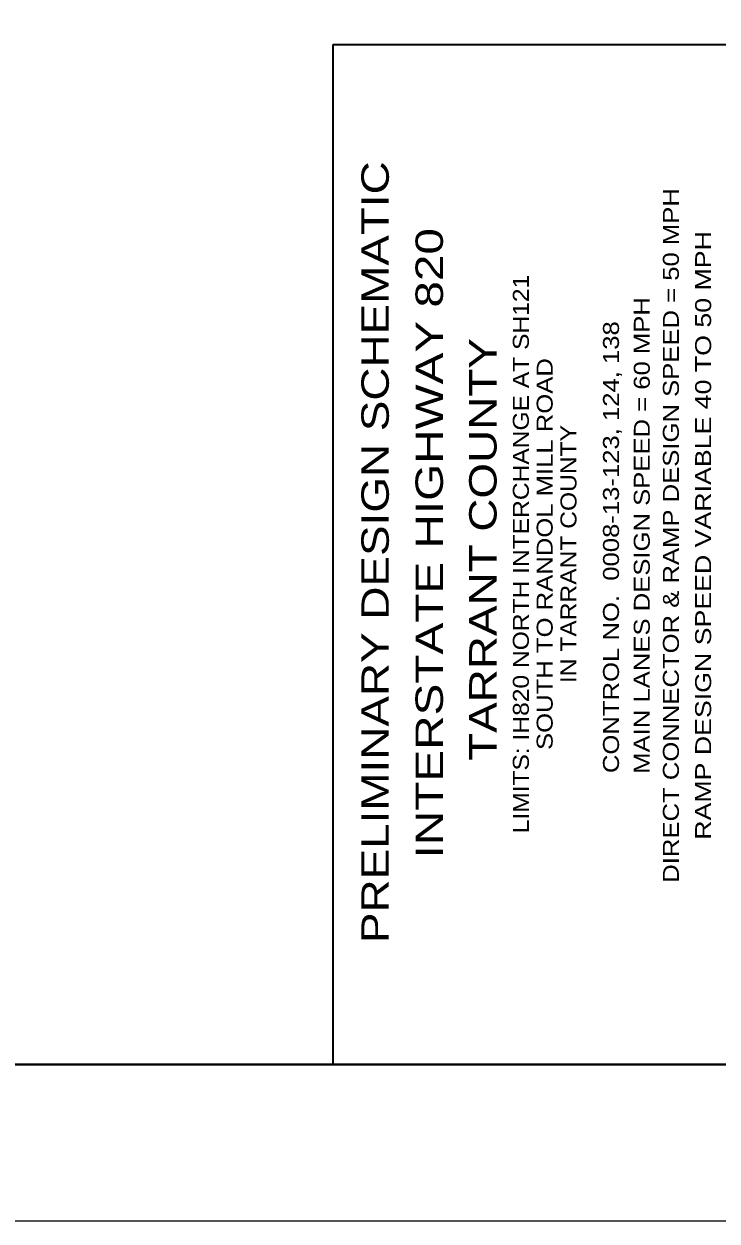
# Model space of a CAD drawing. Extents: x 2363323 to 2367082, y 6956018 to 6980837.
# Drawn here: x 2366029 to 2366472, y 6957201 to 6957965 of the extents above; entities that cross this region are included whole.
import ezdxf
from ezdxf.enums import TextEntityAlignment as Align

# ---------------------------------------------------------------- set-up
doc = ezdxf.new("R2010")
doc.units = 0
doc.header["$LTSCALE"] = 4.1
for name, color, linetype, lineweight in [('61', 7, 'Continuous', 40), ('62', 7, 'Continuous', 13), ('63', 7, 'Continuous', 13)]:
    doc.layers.add(name, color=color, linetype=linetype, lineweight=lineweight)

msp = doc.modelspace()

# ---------------------------------------------------------------- linework, layer by layer
at = {"layer": '61'}
msp.add_line((2366823.34, 6957300.912), (2363423.186, 6957300.912), dxfattribs=at)
msp.add_line((2366823.34, 6957300.912), (2363423.186, 6957300.912), dxfattribs=at)
at = {"layer": '61', "lineweight": 13}
msp.add_lwpolyline([(2366923.344, 6957200.912), (2363323.182, 6957200.912), (2363323.182, 6980256.082)], dxfattribs=at)
at = {"layer": '62', "lineweight": 35}
for p, q in [((2366226.481, 6957951.933), (2366823.339, 6957951.933)), ((2366226.482, 6957300.912), (2366226.481, 6957951.933))]:
    msp.add_line(p, q, dxfattribs=at)
at = {"layer": '63', "lineweight": 35}
for p, q in [((2366226.482, 6957300.912), (2366226.481, 6957951.933)), ((2366226.481, 6957951.933), (2366823.339, 6957951.933))]:
    msp.add_line(p, q, dxfattribs=at)

# ---------------------------------------------------------------- texts
at = {"layer": '61'}
for s, width, p in [('LIMITS: IH820 NORTH INTERCHANGE AT SH121', 1.15, (2366351.432, 6957626.649)), ('SOUTH TO RANDOL MILL ROAD', 1.2, (2366366.632, 6957626.649)), ('IN TARRANT COUNTY', 1.15, (2366381.832, 6957626.649))]:
    msp.add_text(s, height=10.2, rotation=90, dxfattribs=dict(at, width=width)).set_placement(p, align=Align.CENTER)
at = {"layer": '62'}
for s, height, width, p in [('PRELIMINARY DESIGN SCHEMATIC', 17.5, 1.25, (2366262.034, 6957378.352)), ('INTERSTATE HIGHWAY 820', 17.5, 1.3, (2366296.572, 6957432.394)), ('CONTROL NO.  0008-13-123, 124, 138', 10.2, 1.2, (2366408.975, 6957486.85)), ('TARRANT COUNTY', 17.5, 1.25, (2366330.827, 6957494.663))]:
    msp.add_text(s, height=height, rotation=90, dxfattribs=dict(at, width=width)).set_placement(p)
for s, width, p in [('DIRECT CONNECTOR & RAMP DESIGN SPEED = 50 MPH', 1.2, (2366447.22, 6957638.533)), ('RAMP DESIGN SPEED VARIABLE 40 TO 50 MPH', 1.25, (2366467.796, 6957638.533)), ('MAIN LANES DESIGN SPEED = 60 MPH', 1.2, (2366428.642, 6957638.534))]:
    msp.add_text(s, height=10.2, rotation=90, dxfattribs=dict(at, width=width)).set_placement(p, align=Align.CENTER)
at = {"layer": '63', "width": 1.2}
for s, p in [('DIRECT CONNECTOR & RAMP DESIGN SPEED = 50 MPH', (2366447.22, 6957638.533)), ('MAIN LANES DESIGN SPEED = 60 MPH', (2366428.642, 6957638.534))]:
    msp.add_text(s, height=10.2, rotation=90, dxfattribs=at).set_placement(p, align=Align.CENTER)

doc.saveas('drawing.dxf')
